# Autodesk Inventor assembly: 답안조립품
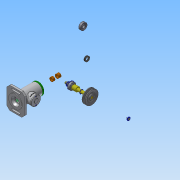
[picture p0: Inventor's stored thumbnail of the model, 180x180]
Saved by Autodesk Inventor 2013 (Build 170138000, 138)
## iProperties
Created: 2017-10
Part Number: 답안조립품
Document SubType Name: Assembly
Designer: Administrator
Author: Administrator
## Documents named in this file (20)
- C:\Users\Administrator\Desktop\471008V1014\답안조립품.iam
- C:\Users\Administrator\Desktop\471008V1014\V-벨트풀리.ipt
- C:\Users\Administrator\Desktop\471008V1014\너트 M10.ipt
- C:\Users\Administrator\Desktop\471008V1014\멈춤링 15 x 1.ipt
- C:\Users\Administrator\Desktop\471008V1014\멈춤링 35x1.6.ipt
- C:\Users\Administrator\Desktop\471008V1014\베어링 15 x 35 x 11.ipt
- C:\Users\Administrator\Desktop\471008V1014\본체.ipt
- C:\Users\Administrator\Desktop\471008V1014\볼트 M4 x 10.ipt
- C:\Users\Administrator\Desktop\471008V1014\부시1.ipt
- C:\Users\Administrator\Desktop\471008V1014\부시2.ipt
- C:\Users\Administrator\Desktop\471008V1014\사이드 커버.ipt
- 사이드 커버.ipt
- C:\Users\Administrator\Desktop\471008V1014\십자볼트 M3 x 10.ipt
- C:\Users\Administrator\Desktop\471008V1014\오일 실 15 25 7.ipt
- C:\Users\Administrator\Desktop\471008V1014\와셔 3x6.ipt
- C:\Users\Administrator\Desktop\471008V1014\와셔 4x16.ipt
- C:\Users\Administrator\Desktop\471008V1014\와셔 10x21.ipt
- C:\Users\Administrator\Desktop\471008V1014\축.ipt
- C:\Users\Administrator\Desktop\471008V1014\키 4 x 4 x 18.ipt
- C:\Users\Administrator\Desktop\471008V1014\탑 커버.ipt
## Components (2 placed, 2 different names)
1. V-벨트풀리:1
2. ISO 4017 M4 x 10:1
